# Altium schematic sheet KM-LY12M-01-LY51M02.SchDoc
size A4
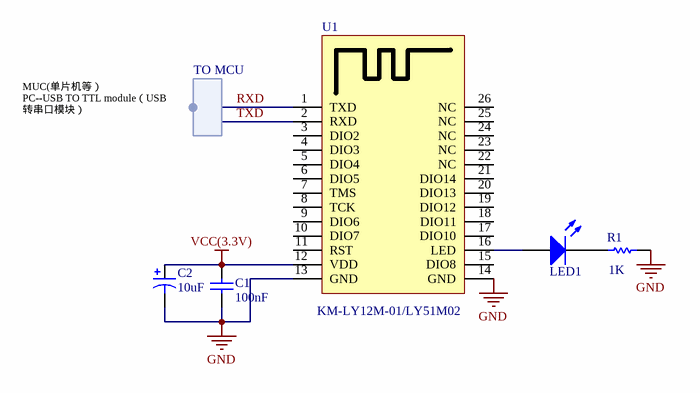
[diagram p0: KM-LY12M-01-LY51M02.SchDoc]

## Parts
?  LED1  [LED-0]
C1  value 100nF  [RAD-0.3]  (hidden comment: Cap)
C2  value 10uF  [RB7.6-15]  (hidden comment: Cap Pol1)
R1  value 1K  [AXIAL-0.3]  (hidden comment: Res1)
U1  KM-LY12M-01/LY51M02

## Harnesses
TO MCU: 

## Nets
GND: C1.1 C2.2 R1.2 U1.13(GND) U1.14(GND)
VCC(3.3V): C1.2 C2.1 U1.12(VDD)
RXD: U1.1(TXD)
TXD: U1.2(RXD)
Net?_1: ?.1(A) U1.16(LED)
Net?_2: ?.2(K) R1.1

Not connected (* = marked no-connect by the designer): U1 3(DIO2) 4(DIO3) 5(DIO4) 6(DIO5) 7(TMS) 8(TCK) 9(DIO6) 10(DIO7) 11(RST) 15(DIO8) 17(DIO10) 18(DIO11) 19(DIO12) 20(DIO13) 21(DIO14) 22(NC) 23(NC) 24(NC) 25(NC) 26(NC)

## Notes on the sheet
- MUC(单片机等）
  PC--USB TO TTL module（USB 转串口模块）

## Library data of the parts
? = LED0: Typical INFRARED GaAs LED
C1 = Cap: Capacitor
C2 = Cap Pol1: Polarized Capacitor (Radial)
R1 = Res1: Resistor
U1 = LY51M02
